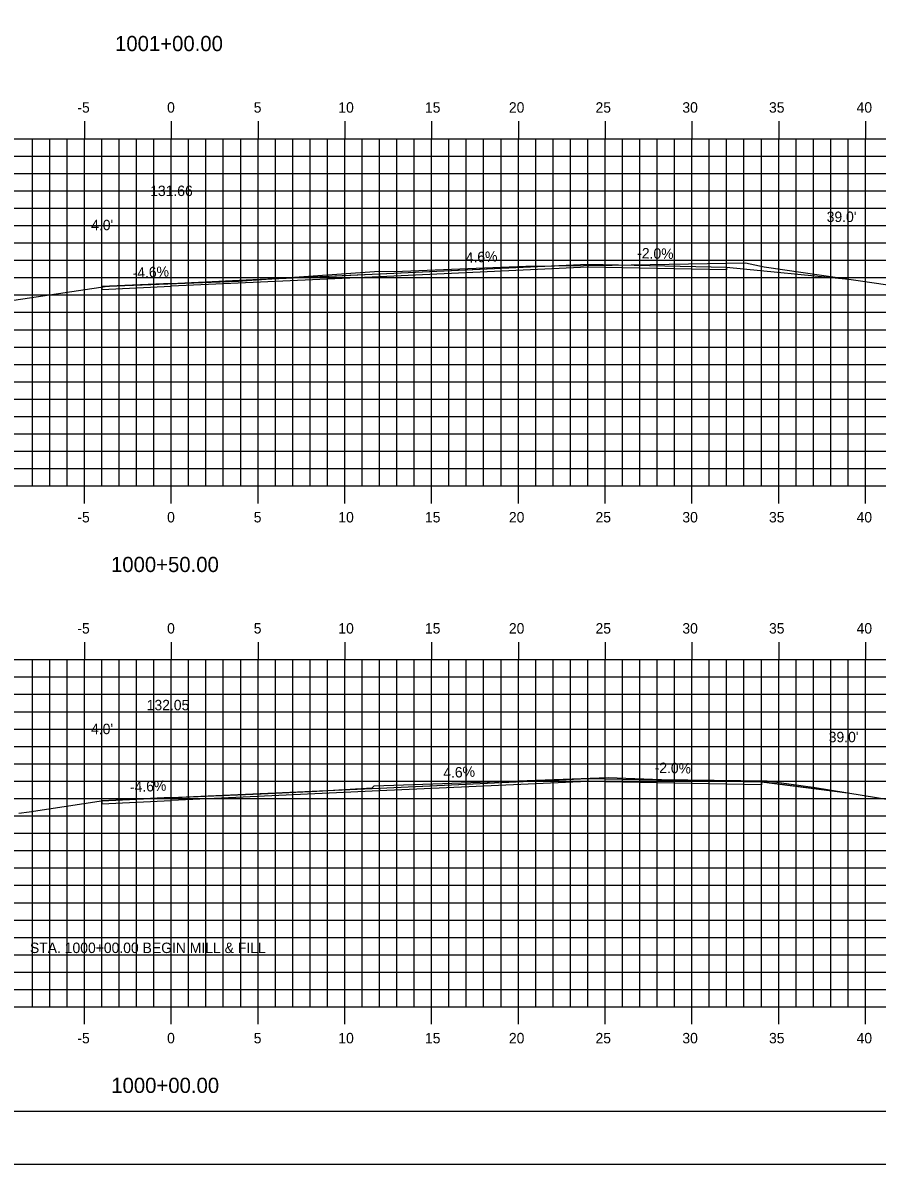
# Model space of a CAD drawing. Extents: x 850630 to 850801, y 365624 to 365734.
# Drawn here: x 850704.2 to 850753.4, y 365624 to 365689.7 of the extents above; entities that cross this region are included whole.
import ezdxf

# ---------------------------------------------------------------- set-up
doc = ezdxf.new("R2010")
doc.units = 0
for name, color, linetype in [('ANNOTATION', 7, 'Continuous'), ('BORDER', 7, 'Continuous'), ('D_Roadway_Centerline', 7, 'Continuous'), ('D_Roadway_Centerline_Text', 7, 'Continuous'), ('D_Roadway_Edge_Shoulder', 7, 'Continuous'), ('D_Roadway_Edge_TW', 7, 'Continuous'), ('D_Roadway_FinishedGrade', 7, 'Continuous'), ('D_Text_Standard', 7, 'Continuous'), ('H_V ANNOTATION', 7, 'Continuous'), ('M_Roadway_Centerline', 7, 'Continuous'), ('MAJOR', 7, 'Continuous'), ('MINOR', 7, 'Continuous'), ('PLOT BOUNDARY', 7, 'Continuous'), ('S_Roadway_Centerline', 7, 'Continuous')]:
    doc.layers.add(name, color=color, linetype=linetype)

msp = doc.modelspace()

# ---------------------------------------------------------------- linework, layer by layer
at = {"layer": 'BORDER'}
msp.add_lwpolyline([(850637.74, 365627.027), (850797.74, 365627.027), (850797.74, 365732.027), (850637.74, 365732.027)], close=True, dxfattribs=at)
at = {"layer": 'D_Roadway_Centerline'}
for points in [[(850708.738, 365674.508), (850712.74, 365674.692), (850712.742, 365674.692), (850717.432, 365674.908), (850724.739, 365675.244), (850730.907, 365675.527), (850736.736, 365675.796), (850736.739, 365675.796), (850744.738, 365675.636), (850744.739, 365675.636)], [(850727.244, 365645.744), (850736.735, 365646.181), (850736.74, 365646.181), (850736.744, 365646.181), (850746.739, 365645.981)], [(850708.738, 365644.893), (850712.739, 365645.077), (850722.152, 365645.51)]]:
    msp.add_lwpolyline(points, dxfattribs=at)
at = {"layer": 'D_Roadway_Edge_Shoulder'}
for points in [[(850736.739, 365675.796), (850744.739, 365675.636), (850744.739, 365675.469), (850736.739, 365675.629)], [(850712.74, 365674.692), (850708.739, 365674.508), (850708.739, 365674.341), (850712.74, 365674.525)], [(850736.74, 365646.181), (850746.739, 365645.981), (850746.739, 365645.815), (850736.74, 365646.015)], [(850712.739, 365645.077), (850708.739, 365644.893), (850708.739, 365644.727), (850712.739, 365644.911)]]:
    msp.add_lwpolyline(points, close=True, dxfattribs=at)
at = {"layer": 'D_Roadway_Edge_TW'}
for points in [[(850724.739, 365675.244), (850736.739, 365675.796), (850736.739, 365675.629), (850724.739, 365675.077)], [(850712.74, 365674.692), (850724.739, 365675.244), (850724.739, 365675.077), (850712.74, 365674.525)], [(850724.739, 365645.629), (850736.74, 365646.181), (850736.74, 365646.015), (850724.739, 365645.463)], [(850712.739, 365645.077), (850724.739, 365645.629), (850724.739, 365645.463), (850712.739, 365644.911)]]:
    msp.add_lwpolyline(points, close=True, dxfattribs=at)
for points in [[(850724.739, 365675.244), (850724.739, 365675.077)], [(850724.739, 365645.629), (850724.739, 365645.463)]]:
    msp.add_lwpolyline(points, dxfattribs=at)
at = {"layer": 'D_Roadway_FinishedGrade'}
for p, q in [((850744.739, 365675.636), (850751.78, 365674.932)), ((850746.739, 365645.981), (850751.704, 365645.36))]:
    msp.add_line(p, q, dxfattribs=at)
at = {"layer": 'D_Text_Standard'}
msp.add_line((850751.717, 365645.343), (850746.739, 365645.981), dxfattribs=at)
at = {"layer": 'MAJOR'}
for p, q in [((850707.739, 365684.029), (850707.739, 365683.027)), ((850712.739, 365684.029), (850712.739, 365683.027)), ((850717.739, 365684.029), (850717.739, 365683.027)), ((850722.739, 365684.029), (850722.739, 365683.027)), ((850727.739, 365684.029), (850727.739, 365683.027)), ((850732.739, 365684.029), (850732.739, 365683.027)), ((850737.739, 365684.029), (850737.739, 365683.027)), ((850742.739, 365684.029), (850742.739, 365683.027)), ((850747.739, 365684.029), (850747.739, 365683.027)), ((850752.739, 365684.029), (850752.739, 365683.027)), ((850642.739, 365683.027), (850782.739, 365683.027)), ((850642.739, 365683.027), (850782.739, 365683.027)), ((850707.739, 365663.027), (850707.739, 365683.027)), ((850712.739, 365663.027), (850712.739, 365683.027)), ((850717.739, 365663.027), (850717.739, 365683.027)), ((850722.739, 365663.027), (850722.739, 365683.027)), ((850727.739, 365663.027), (850727.739, 365683.027)), ((850732.739, 365663.027), (850732.739, 365683.027)), ((850737.739, 365663.027), (850737.739, 365683.027)), ((850742.739, 365663.027), (850742.739, 365683.027)), ((850747.739, 365663.027), (850747.739, 365683.027)), ((850752.739, 365663.027), (850752.739, 365683.027)), ((850642.739, 365678.027), (850782.739, 365678.027)), ((850642.739, 365673.027), (850782.739, 365673.027)), ((850642.739, 365668.027), (850782.739, 365668.027)), ((850642.739, 365663.027), (850782.739, 365663.027)), ((850642.739, 365663.027), (850782.739, 365663.027)), ((850707.739, 365662.025), (850707.739, 365663.027)), ((850712.739, 365662.025), (850712.739, 365663.027)), ((850717.739, 365662.025), (850717.739, 365663.027)), ((850722.739, 365662.025), (850722.739, 365663.027)), ((850727.739, 365662.025), (850727.739, 365663.027)), ((850732.739, 365662.025), (850732.739, 365663.027)), ((850737.739, 365662.025), (850737.739, 365663.027)), ((850742.739, 365662.025), (850742.739, 365663.027)), ((850747.739, 365662.025), (850747.739, 365663.027)), ((850752.739, 365662.025), (850752.739, 365663.027)), ((850707.739, 365654.029), (850707.739, 365653.027)), ((850712.739, 365654.029), (850712.739, 365653.027)), ((850717.739, 365654.029), (850717.739, 365653.027)), ((850722.739, 365654.029), (850722.739, 365653.027)), ((850727.739, 365654.029), (850727.739, 365653.027)), ((850732.739, 365654.029), (850732.739, 365653.027)), ((850737.739, 365654.029), (850737.739, 365653.027)), ((850742.739, 365654.029), (850742.739, 365653.027)), ((850747.739, 365654.029), (850747.739, 365653.027)), ((850752.739, 365654.029), (850752.739, 365653.027)), ((850642.739, 365653.027), (850782.739, 365653.027)), ((850642.739, 365653.027), (850782.739, 365653.027)), ((850707.739, 365633.027), (850707.739, 365653.027)), ((850712.739, 365633.027), (850712.739, 365653.027)), ((850717.739, 365633.027), (850717.739, 365653.027)), ((850722.739, 365633.027), (850722.739, 365653.027)), ((850727.739, 365633.027), (850727.739, 365653.027)), ((850732.739, 365633.027), (850732.739, 365653.027)), ((850737.739, 365633.027), (850737.739, 365653.027)), ((850742.739, 365633.027), (850742.739, 365653.027)), ((850747.739, 365633.027), (850747.739, 365653.027)), ((850752.739, 365633.027), (850752.739, 365653.027)), ((850642.739, 365648.027), (850782.739, 365648.027)), ((850642.739, 365643.027), (850782.739, 365643.027)), ((850642.739, 365638.027), (850782.739, 365638.027)), ((850642.739, 365633.027), (850782.739, 365633.027)), ((850642.739, 365633.027), (850782.739, 365633.027)), ((850707.739, 365632.025), (850707.739, 365633.027)), ((850712.739, 365632.025), (850712.739, 365633.027)), ((850717.739, 365632.025), (850717.739, 365633.027)), ((850722.739, 365632.025), (850722.739, 365633.027)), ((850727.739, 365632.025), (850727.739, 365633.027)), ((850732.739, 365632.025), (850732.739, 365633.027)), ((850737.739, 365632.025), (850737.739, 365633.027)), ((850742.739, 365632.025), (850742.739, 365633.027)), ((850747.739, 365632.025), (850747.739, 365633.027)), ((850752.739, 365632.025), (850752.739, 365633.027))]:
    msp.add_line(p, q, dxfattribs=at)
at = {"layer": 'MINOR'}
for p, q in [((850704.739, 365663.027), (850704.739, 365683.027)), ((850705.739, 365663.027), (850705.739, 365683.027)), ((850706.739, 365663.027), (850706.739, 365683.027)), ((850708.739, 365663.027), (850708.739, 365683.027)), ((850709.739, 365663.027), (850709.739, 365683.027)), ((850710.739, 365663.027), (850710.739, 365683.027)), ((850711.739, 365663.027), (850711.739, 365683.027)), ((850713.739, 365663.027), (850713.739, 365683.027)), ((850714.739, 365663.027), (850714.739, 365683.027)), ((850715.739, 365663.027), (850715.739, 365683.027)), ((850716.739, 365663.027), (850716.739, 365683.027)), ((850718.739, 365663.027), (850718.739, 365683.027)), ((850719.739, 365663.027), (850719.739, 365683.027)), ((850720.739, 365663.027), (850720.739, 365683.027)), ((850721.739, 365663.027), (850721.739, 365683.027)), ((850723.739, 365663.027), (850723.739, 365683.027)), ((850724.739, 365663.027), (850724.739, 365683.027)), ((850725.739, 365663.027), (850725.739, 365683.027)), ((850726.739, 365663.027), (850726.739, 365683.027)), ((850728.739, 365663.027), (850728.739, 365683.027)), ((850729.739, 365663.027), (850729.739, 365683.027)), ((850730.739, 365663.027), (850730.739, 365683.027)), ((850731.739, 365663.027), (850731.739, 365683.027)), ((850733.739, 365663.027), (850733.739, 365683.027)), ((850734.739, 365663.027), (850734.739, 365683.027)), ((850735.739, 365663.027), (850735.739, 365683.027)), ((850736.739, 365663.027), (850736.739, 365683.027)), ((850738.739, 365663.027), (850738.739, 365683.027)), ((850739.739, 365663.027), (850739.739, 365683.027)), ((850740.739, 365663.027), (850740.739, 365683.027)), ((850741.739, 365663.027), (850741.739, 365683.027)), ((850743.739, 365663.027), (850743.739, 365683.027)), ((850744.739, 365663.027), (850744.739, 365683.027)), ((850745.739, 365663.027), (850745.739, 365683.027)), ((850746.739, 365663.027), (850746.739, 365683.027)), ((850748.739, 365663.027), (850748.739, 365683.027)), ((850749.739, 365663.027), (850749.739, 365683.027)), ((850750.739, 365663.027), (850750.739, 365683.027)), ((850751.739, 365663.027), (850751.739, 365683.027)), ((850642.739, 365682.027), (850782.739, 365682.027)), ((850642.739, 365681.027), (850782.739, 365681.027)), ((850642.739, 365680.027), (850782.739, 365680.027)), ((850642.739, 365679.027), (850782.739, 365679.027)), ((850642.739, 365677.027), (850782.739, 365677.027)), ((850642.739, 365676.027), (850782.739, 365676.027)), ((850642.739, 365675.027), (850782.739, 365675.027)), ((850642.739, 365674.027), (850782.739, 365674.027)), ((850642.739, 365672.027), (850782.739, 365672.027)), ((850642.739, 365671.027), (850782.739, 365671.027)), ((850642.739, 365670.027), (850782.739, 365670.027)), ((850642.739, 365669.027), (850782.739, 365669.027)), ((850642.739, 365667.027), (850782.739, 365667.027)), ((850642.739, 365666.027), (850782.739, 365666.027)), ((850642.739, 365665.027), (850782.739, 365665.027)), ((850642.739, 365664.027), (850782.739, 365664.027)), ((850704.739, 365633.027), (850704.739, 365653.027)), ((850705.739, 365633.027), (850705.739, 365653.027)), ((850706.739, 365633.027), (850706.739, 365653.027)), ((850708.739, 365633.027), (850708.739, 365653.027)), ((850709.739, 365633.027), (850709.739, 365653.027)), ((850710.739, 365633.027), (850710.739, 365653.027)), ((850711.739, 365633.027), (850711.739, 365653.027)), ((850713.739, 365633.027), (850713.739, 365653.027)), ((850714.739, 365633.027), (850714.739, 365653.027)), ((850715.739, 365633.027), (850715.739, 365653.027)), ((850716.739, 365633.027), (850716.739, 365653.027)), ((850718.739, 365633.027), (850718.739, 365653.027)), ((850719.739, 365633.027), (850719.739, 365653.027)), ((850720.739, 365633.027), (850720.739, 365653.027)), ((850721.739, 365633.027), (850721.739, 365653.027)), ((850723.739, 365633.027), (850723.739, 365653.027)), ((850724.739, 365633.027), (850724.739, 365653.027)), ((850725.739, 365633.027), (850725.739, 365653.027)), ((850726.739, 365633.027), (850726.739, 365653.027)), ((850728.739, 365633.027), (850728.739, 365653.027)), ((850729.739, 365633.027), (850729.739, 365653.027)), ((850730.739, 365633.027), (850730.739, 365653.027)), ((850731.739, 365633.027), (850731.739, 365653.027)), ((850733.739, 365633.027), (850733.739, 365653.027)), ((850734.739, 365633.027), (850734.739, 365653.027)), ((850735.739, 365633.027), (850735.739, 365653.027)), ((850736.739, 365633.027), (850736.739, 365653.027)), ((850738.739, 365633.027), (850738.739, 365653.027)), ((850739.739, 365633.027), (850739.739, 365653.027)), ((850740.739, 365633.027), (850740.739, 365653.027)), ((850741.739, 365633.027), (850741.739, 365653.027)), ((850743.739, 365633.027), (850743.739, 365653.027)), ((850744.739, 365633.027), (850744.739, 365653.027)), ((850745.739, 365633.027), (850745.739, 365653.027)), ((850746.739, 365633.027), (850746.739, 365653.027)), ((850748.739, 365633.027), (850748.739, 365653.027)), ((850749.739, 365633.027), (850749.739, 365653.027)), ((850750.739, 365633.027), (850750.739, 365653.027)), ((850751.739, 365633.027), (850751.739, 365653.027)), ((850642.739, 365652.027), (850782.739, 365652.027)), ((850642.739, 365651.027), (850782.739, 365651.027)), ((850642.739, 365650.027), (850782.739, 365650.027)), ((850642.739, 365649.027), (850782.739, 365649.027)), ((850642.739, 365647.027), (850782.739, 365647.027)), ((850642.739, 365646.027), (850782.739, 365646.027)), ((850642.739, 365645.027), (850782.739, 365645.027)), ((850642.739, 365644.027), (850782.739, 365644.027)), ((850642.739, 365642.027), (850782.739, 365642.027)), ((850642.739, 365641.027), (850782.739, 365641.027)), ((850642.739, 365640.027), (850782.739, 365640.027)), ((850642.739, 365639.027), (850782.739, 365639.027)), ((850642.739, 365637.027), (850782.739, 365637.027)), ((850642.739, 365636.027), (850782.739, 365636.027)), ((850642.739, 365635.027), (850782.739, 365635.027)), ((850642.739, 365634.027), (850782.739, 365634.027))]:
    msp.add_line(p, q, dxfattribs=at)
at = {"layer": 'PLOT BOUNDARY'}
msp.add_lwpolyline([(850629.646, 365623.968), (850799.646, 365623.968), (850799.646, 365733.968), (850629.646, 365733.968)], close=True, dxfattribs=at)
at = {"layer": 'S_Roadway_Centerline'}
for points in [[(850701.203, 365673.361), (850709.069, 365674.533), (850715.031, 365674.764), (850716.605, 365674.827), (850716.849, 365674.849), (850724.444, 365675.377), (850726.057, 365675.398), (850730.303, 365675.565), (850733.164, 365675.676), (850738.143, 365675.748), (850745.83, 365675.875), (850746.894, 365675.65), (850751.259, 365675.008), (850757.573, 365674.085), (850768.246, 365672.41), (850771.008, 365671.981), (850781.056, 365670.333), (850782.47, 365670.35), (850782.739, 365670.436)], [(850703.949, 365644.184), (850704.554, 365644.269), (850708.843, 365644.91), (850717.92, 365645.299), (850721.12, 365645.442), (850724.315, 365645.639), (850724.424, 365645.75), (850728.366, 365645.886), (850733.24, 365646.073), (850737.922, 365646.231), (850740.995, 365646.115), (850747.079, 365646.044), (850749.84, 365645.665), (850769.738, 365642.41), (850772.848, 365641.887), (850779.607, 365640.904), (850780.748, 365640.734), (850780.919, 365640.742), (850782.739, 365641.37)]]:
    msp.add_lwpolyline(points, dxfattribs=at)

# ---------------------------------------------------------------- texts
at = {"layer": 'ANNOTATION'}
for s, rotation, p in [('-2.0%', 358.85426, (850739.581, 365676.139)), ('4.6%', 2.63382, (850729.719, 365675.874)), ('-4.6%', 2.63333, (850710.526, 365674.991)), ('4.6%', 2.63368, (850728.425, 365646.199)), ('-2.0%', 358.85422, (850740.584, 365646.504)), ('-4.6%', 2.6338, (850710.371, 365645.382))]:
    msp.add_text(s, height=0.6, rotation=rotation, dxfattribs=at).set_placement(p)
msp.add_text('STA. 1000+00.00 BEGIN MILL & FILL', height=0.6, dxfattribs=at).set_placement((850704.597, 365636.127))
at = {"layer": 'D_Roadway_Centerline'}
for s, p in [('C', (850712.735, 365674.692)), ('L', (850712.74, 365674.684)), ('C', (850712.734, 365645.077)), ('L', (850712.739, 365645.069))]:
    msp.add_text(s, height=0.0146, dxfattribs=at).set_placement(p)
at = {"layer": 'D_Roadway_Centerline_Text'}
for s, p in [('131.66', (850711.525, 365679.724)), ('132.05', (850711.324, 365650.109))]:
    msp.add_text(s, height=0.6, dxfattribs=at).set_placement(p)
at = {"layer": 'D_Text_Standard'}
for s, p in [("39.0'", (850750.504, 365678.23)), ("4.0'", (850708.125, 365677.756)), ("4.0'", (850708.118, 365648.732)), ("39.0'", (850750.621, 365648.267))]:
    msp.add_text(s, height=0.6, dxfattribs=at).set_placement(p)
at = {"layer": 'H_V ANNOTATION'}
for s, height, p in [('1001+00.00', 0.875, (850709.501, 365688.07)), ('-5', 0.6, (850707.33, 365684.527)), ('0', 0.6, (850712.499, 365684.527)), ('5', 0.6, (850717.491, 365684.527)), ('10', 0.6, (850722.365, 365684.527)), ('15', 0.6, (850727.357, 365684.527)), ('20', 0.6, (850732.193, 365684.527)), ('25', 0.6, (850737.185, 365684.527)), ('30', 0.6, (850742.188, 365684.527)), ('35', 0.6, (850747.18, 365684.527)), ('40', 0.6, (850752.226, 365684.527)), ('-5', 0.6, (850707.33, 365660.927)), ('0', 0.6, (850712.499, 365660.927)), ('5', 0.6, (850717.491, 365660.927)), ('10', 0.6, (850722.365, 365660.927)), ('15', 0.6, (850727.357, 365660.927)), ('20', 0.6, (850732.193, 365660.927)), ('25', 0.6, (850737.185, 365660.927)), ('30', 0.6, (850742.188, 365660.927)), ('35', 0.6, (850747.18, 365660.927)), ('40', 0.6, (850752.226, 365660.927)), ('1000+50.00', 0.875, (850709.267, 365658.07)), ('-5', 0.6, (850707.33, 365654.527)), ('0', 0.6, (850712.499, 365654.527)), ('5', 0.6, (850717.491, 365654.527)), ('10', 0.6, (850722.365, 365654.527)), ('15', 0.6, (850727.357, 365654.527)), ('20', 0.6, (850732.193, 365654.527)), ('25', 0.6, (850737.185, 365654.527)), ('30', 0.6, (850742.188, 365654.527)), ('35', 0.6, (850747.18, 365654.527)), ('40', 0.6, (850752.226, 365654.527)), ('-5', 0.6, (850707.33, 365630.927)), ('0', 0.6, (850712.499, 365630.927)), ('5', 0.6, (850717.491, 365630.927)), ('10', 0.6, (850722.365, 365630.927)), ('15', 0.6, (850727.357, 365630.927)), ('20', 0.6, (850732.193, 365630.927)), ('25', 0.6, (850737.185, 365630.927)), ('30', 0.6, (850742.188, 365630.927)), ('35', 0.6, (850747.18, 365630.927)), ('40', 0.6, (850752.226, 365630.927)), ('1000+00.00', 0.875, (850709.283, 365628.07))]:
    msp.add_text(s, height=height, dxfattribs=at).set_placement(p)
at = {"layer": 'M_Roadway_Centerline'}
for s, p in [('C', (850724.438, 365675.377)), ('L', (850724.444, 365675.369)), ('C', (850724.419, 365645.75)), ('L', (850724.424, 365645.742))]:
    msp.add_text(s, height=0.0146, dxfattribs=at).set_placement(p)

doc.saveas('drawing.dxf')
